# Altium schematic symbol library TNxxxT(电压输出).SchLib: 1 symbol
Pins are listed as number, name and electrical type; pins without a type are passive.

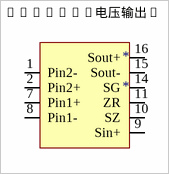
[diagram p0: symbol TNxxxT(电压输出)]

## TNxxxT(电压输出)
designator *
pins: 1 Pin2-, 2 Pin2+, 7 Pin1+, 8 Pin1-, 9 Sin+, 10 SZ, 11 ZR, 14 SG, 15 Sout-, 16 Sout+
